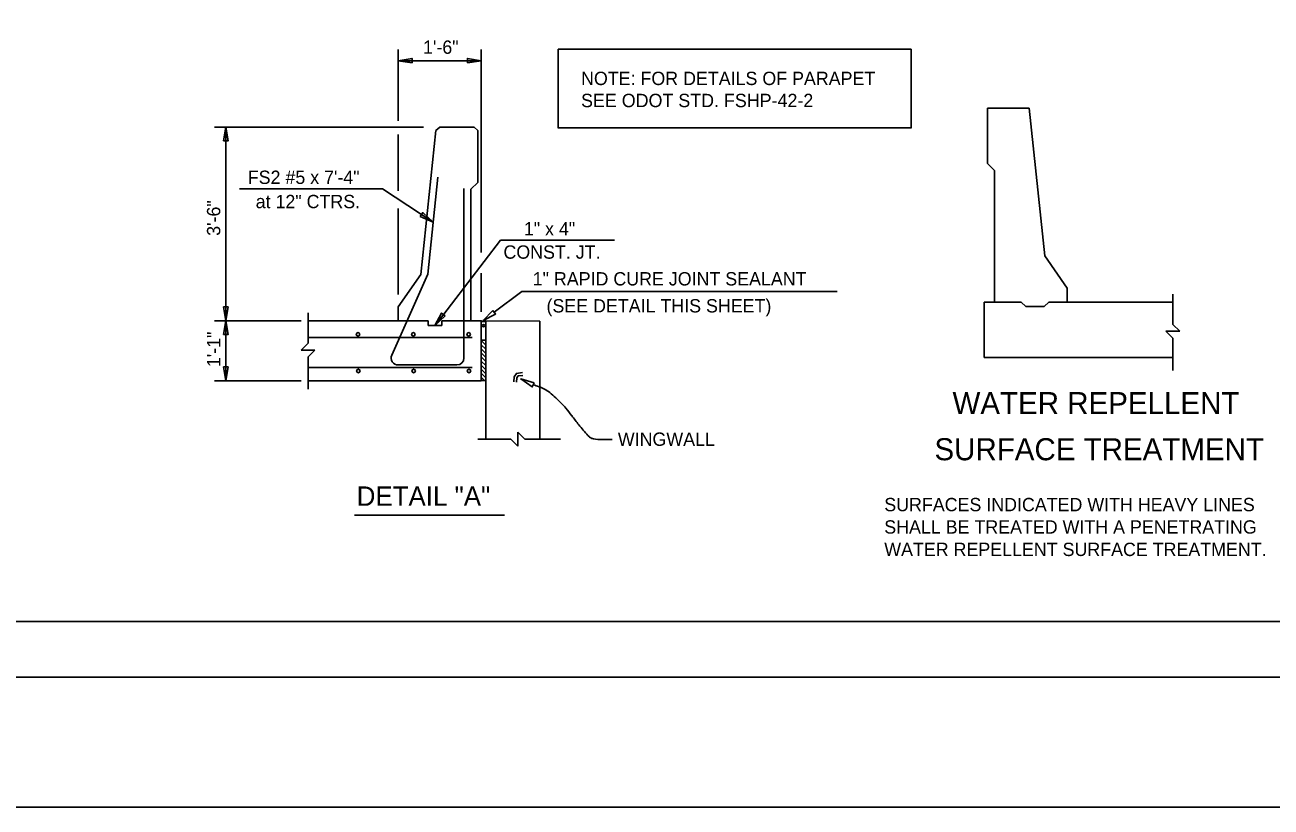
# Model space of a CAD drawing. Extents: x 570 to 2152770, y -27 to 139926.
# Drawn here: x 2151140 to 2151230, y 138735.3 to 138791.8 of the extents above; entities that cross this region are included whole.
import ezdxf

# ---------------------------------------------------------------- set-up
doc = ezdxf.new("R2010")
doc.units = 0
for name, color, linetype in [('2', 7, 'Continuous'), ('4', 7, 'Continuous'), ('5', 7, 'Continuous'), ('6', 7, 'Continuous'), ('Default', 7, 'Continuous'), ('PR_Dimensions', 7, 'Continuous'), ('PR_Reinforcing', 7, 'Continuous'), ('SHT_Plot_Shape_Full', 7, 'Continuous'), ('SHT_Plot_Shape_Half', 7, 'Continuous'), ('SHT_Sheet_Border', 7, 'Continuous'), ('T', 7, 'Continuous')]:
    doc.layers.add(name, color=color, linetype=linetype)

# ---------------------------------------------------------------- blocks, each defined once
blk = doc.blocks.new('DWG01008_2')
at = {"layer": 'Default'}
for p, q in [((-0.0132, 0), (0, 0.0132)), ((0, 0.0132), (0, -0.0132)), ((0, -0.0132), (0.0132, 0))]:
    blk.add_line(p, q, dxfattribs=at)
blk = doc.blocks.new('ARROWHD_7')
at = {"layer": 'Default'}
blk.add_lwpolyline([(0.0261, -0.0045), (0.0261, 0.0043), (-0.0004, -0.0001)], close=True, dxfattribs=at)

msp = doc.modelspace()

# ---------------------------------------------------------------- linework, layer by layer
at = {"layer": '2'}
for p, q in [((2151173.278, 138770.4), (2151173.278, 138761.846)), ((2151173.278, 138770.4), (2151177.175, 138770.362)), ((2151177.175, 138770.362), (2151177.175, 138761.846))]:
    msp.add_line(p, q, dxfattribs=at)
at = {"layer": '4'}
for p, q in [((2151169.668, 138784.15), (2151168.57, 138773.733)), ((2151169.945, 138784.399), (2151169.668, 138784.15)), ((2151172.445, 138784.399), (2151169.945, 138784.399)), ((2151172.445, 138784.399), (2151172.695, 138784.149)), ((2151172.695, 138780.399), (2151172.695, 138784.149)), ((2151172.695, 138780.399), (2151172.195, 138779.899)), ((2151172.195, 138770.4), (2151172.195, 138779.899)), ((2151168.57, 138773.733), (2151166.945, 138771.399)), ((2151166.945, 138770.4), (2151166.945, 138771.399)), ((2151169.111, 138770.4), (2151160.433, 138770.4)), ((2151169.111, 138770.4), (2151169.111, 138770.066)), ((2151170.111, 138770.066), (2151169.111, 138770.066)), ((2151172.945, 138770.4), (2151170.111, 138770.4)), ((2151170.111, 138770.4), (2151170.111, 138770.066)), ((2151172.945, 138770.4), (2151172.945, 138766.066)), ((2151172.945, 138766.066), (2151160.433, 138766.066)), ((2151163.784, 138756.34), (2151174.64, 138756.34))]:
    msp.add_line(p, q, dxfattribs=at)
at = {"layer": '5'}
msp.add_lwpolyline([(2151215.295, 138771.752), (2151215.295, 138772.752), (2151213.67, 138775.085), (2151212.545, 138785.751), (2151209.545, 138785.751)], dxfattribs=at)
at = {"layer": '6'}
for p, q in [((2151209.545, 138781.751), (2151209.545, 138785.751)), ((2151209.545, 138781.751), (2151210.045, 138781.251)), ((2151210.045, 138771.752), (2151210.045, 138781.251)), ((2151209.963, 138771.752), (2151209.297, 138771.752)), ((2151209.297, 138771.752), (2151209.297, 138767.753)), ((2151209.963, 138771.752), (2151211.965, 138771.752)), ((2151211.965, 138771.752), (2151212.298, 138771.419)), ((2151213.964, 138771.752), (2151213.631, 138771.419)), ((2151213.964, 138771.752), (2151222.933, 138771.752)), ((2151222.933, 138770.136), (2151222.933, 138772.316)), ((2151212.298, 138771.419), (2151213.631, 138771.419)), ((2151222.933, 138766.803), (2151222.933, 138769.137)), ((2151209.297, 138767.753), (2151222.933, 138767.753))]:
    msp.add_line(p, q, dxfattribs=at)
at = {"layer": 'PR_Dimensions'}
for p, q in [((2151166.945, 138784.851), (2151166.945, 138789.992)), ((2151172.945, 138775.32), (2151172.945, 138789.992)), ((2151172.945, 138789.192), (2151166.945, 138789.192)), ((2151168.777, 138784.399), (2151153.681, 138784.399)), ((2151154.481, 138770.4), (2151154.481, 138784.399)), ((2151166.945, 138779.785), (2151166.945, 138783.853)), ((2151155.478, 138779.93), (2151165.813, 138779.93)), ((2151169.472, 138777.522), (2151165.813, 138779.93)), ((2151166.945, 138772.301), (2151166.945, 138778.504)), ((2151169.611, 138770.066), (2151174.328, 138776.229)), ((2151182.583, 138776.229), (2151174.328, 138776.229)), ((2151172.945, 138771.047), (2151172.945, 138773.842)), ((2151173.886, 138771.009), (2151175.892, 138772.514)), ((2151175.892, 138772.514), (2151198.683, 138772.514)), ((2151160.433, 138768.784), (2151160.433, 138770.964)), ((2151159.933, 138770.4), (2151153.681, 138770.4)), ((2151154.481, 138770.4), (2151154.481, 138766.066)), ((2151159.933, 138770.4), (2151155.295, 138770.4)), ((2151173.278, 138768.985), (2151172.945, 138768.985)), ((2151173.278, 138768.63), (2151172.945, 138768.963)), ((2151173.278, 138768.335), (2151172.945, 138768.668)), ((2151173.278, 138768.04), (2151172.945, 138768.374)), ((2151173.278, 138767.746), (2151172.945, 138768.079)), ((2151160.433, 138765.449), (2151160.433, 138767.784)), ((2151173.278, 138767.451), (2151172.945, 138767.784)), ((2151173.278, 138767.156), (2151172.945, 138767.49)), ((2151173.278, 138766.862), (2151172.945, 138767.195)), ((2151173.278, 138766.567), (2151172.945, 138766.901)), ((2151173.278, 138766.273), (2151172.945, 138766.606)), ((2151173.184, 138766.072), (2151172.945, 138766.311)), ((2151159.933, 138766.066), (2151153.681, 138766.066)), ((2151173.278, 138766.072), (2151172.945, 138766.072)), ((2151175.096, 138761.846), (2151172.692, 138761.846)), ((2151178.679, 138761.846), (2151176.096, 138761.846))]:
    msp.add_line(p, q, dxfattribs=at)
for points in [[(2151167.945, 138789.026), (2151167.945, 138789.359), (2151166.945, 138789.192)], [(2151171.945, 138789.026), (2151171.945, 138789.359), (2151172.945, 138789.192)], [(2151154.315, 138783.399), (2151154.648, 138783.399), (2151154.481, 138784.399)], [(2151168.541, 138777.935), (2151168.725, 138778.215), (2151169.472, 138777.522)], [(2151154.315, 138771.4), (2151154.648, 138771.4), (2151154.481, 138770.4)], [(2151173.786, 138771.142), (2151173.986, 138770.876), (2151173.086, 138770.409)], [(2151154.315, 138769.398), (2151154.648, 138769.398), (2151154.481, 138770.398)], [(2151154.315, 138767.068), (2151154.648, 138767.068), (2151154.481, 138766.068)], [(2151176.78, 138765.919), (2151176.638, 138765.617), (2151175.804, 138766.193)]]:
    msp.add_lwpolyline(points, close=True, dxfattribs=at)
for points in [[(2151175.92, 138766.647), (2151175.487, 138766.598), (2151175.331, 138766.345), (2151175.308, 138765.975)], [(2151175.943, 138766.45), (2151175.606, 138766.411), (2151175.526, 138766.283), (2151175.506, 138765.962)], [(2151182.416, 138761.807), (2151181.701, 138761.807)]]:
    msp.add_lwpolyline(points, dxfattribs=at)
for centre, radius, start, end in [((2151173.112, 138770.573), 0.24, 226.27744, 313.72256), ((2151173.11, 138770.035), 0.0833, 0, 180), ((2151173.11, 138770.035), 0.0833, 180, 0), ((2151175.038, 138760.167), 5.845, 64.82987, 73.38556), ((2151176.841, 138764.005), 1.604, 48.45934, 64.82987), ((2151161.612, 138746.817), 24.569, 45.78007, 48.45934), ((2151175.873, 138761.471), 4.12, 39.23457, 45.78007), ((2151165.538, 138753.031), 17.464, 36.99349, 39.23457), ((2151200.913, 138779.682), 26.827, 216.99349, 218.80165), ((2151195.05, 138774.968), 19.303, 218.80165, 221.75358), ((2151181.405, 138762.788), 1.014, 221.75358, 234.66211), ((2151181.153, 138762.433), 0.578, 234.66211, 260.10442), ((2151181.701, 138765.574), 3.766, 260.10442, 270)]:
    msp.add_arc(centre, radius, start, end, dxfattribs=at)
at = {"layer": 'PR_Reinforcing'}
for p, q in [((2151169.815, 138780.777), (2151169.077, 138773.777)), ((2151171.695, 138779.947), (2151171.695, 138767.707)), ((2151169.077, 138773.777), (2151166.481, 138767.91)), ((2151172.288, 138769.181), (2151160.433, 138769.181)), ((2151172.288, 138767.014), (2151160.433, 138767.014)), ((2151171.195, 138767.207), (2151166.938, 138767.207))]:
    msp.add_line(p, q, dxfattribs=at)
for centre in [(2151164.042, 138769.412), (2151168.043, 138769.411), (2151172.042, 138769.414), (2151164.065, 138766.772), (2151168.062, 138766.773), (2151172.062, 138766.771)]:
    msp.add_circle(centre, 0.127, dxfattribs=at)
for centre, radius, start, end in [((2151164.042, 138769.415), 0.125, 0, 180), ((2151164.042, 138769.415), 0.125, 180, 0), ((2151168.042, 138769.415), 0.125, 0, 180), ((2151168.042, 138769.415), 0.125, 180, 0), ((2151172.042, 138769.415), 0.125, 0, 180), ((2151172.042, 138769.415), 0.125, 180, 0), ((2151166.938, 138767.707), 0.5, 156.12911, 270), ((2151171.195, 138767.707), 0.5, 270, 0), ((2151164.062, 138766.773), 0.125, 0, 180), ((2151164.062, 138766.773), 0.125, 180, 0), ((2151168.062, 138766.773), 0.125, 0, 180), ((2151168.062, 138766.773), 0.125, 180, 0), ((2151172.062, 138766.773), 0.125, 0, 180), ((2151172.062, 138766.773), 0.125, 180, 0)]:
    msp.add_arc(centre, radius, start, end, dxfattribs=at)
at = {"layer": 'SHT_Plot_Shape_Full'}
msp.add_lwpolyline([(2151027.459, 138927.254), (2151315.459, 138927.254), (2151315.459, 138735.254), (2151027.459, 138735.254)], close=True, dxfattribs=at)
at = {"layer": 'SHT_Plot_Shape_Half'}
msp.add_lwpolyline([(2151040.559, 138920.654), (2151312.559, 138920.654), (2151312.559, 138744.654), (2151040.559, 138744.654)], close=True, dxfattribs=at)
at = {"layer": 'SHT_Sheet_Border'}
msp.add_lwpolyline([(2151308.159, 138748.654), (2151056.159, 138748.654), (2151056.159, 138916.654), (2151308.159, 138916.654)], close=True, dxfattribs=at)
at = {"layer": 'T'}
for p, q in [((2151204.028, 138790.018), (2151178.508, 138790.018)), ((2151178.508, 138790.018), (2151178.508, 138784.324)), ((2151204.028, 138784.324), (2151204.028, 138790.018)), ((2151204.028, 138784.35), (2151178.508, 138784.35))]:
    msp.add_line(p, q, dxfattribs=at)

# ---------------------------------------------------------------- block references
at = {"layer": '6', "xscale": 37.78306610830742, "yscale": 37.78306610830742, "rotation": 90}
msp.add_blockref('DWG01008_2', (2151222.933, 138769.637), dxfattribs=at)
at = {"layer": 'PR_Dimensions', "xscale": 37.7952}
for name, p, yscale, rotation in [('ARROWHD_7', (2151169.611, 138770.066), 37.7952, 52.57268367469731), ('DWG01008_2', (2151160.433, 138768.284), -37.7952, 89.99999999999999), ('DWG01008_2', (2151175.596, 138761.846), -37.7952, 180)]:
    msp.add_blockref(name, p, dxfattribs=dict(at, yscale=yscale, rotation=rotation))

# ---------------------------------------------------------------- texts
at = {"layer": '4'}
for s, height, p in [('WATER REPELLENT', 1.59462, (2151207.007, 138763.649)), ('SURFACE TREATMENT', 1.59462, (2151205.702, 138760.317)), ('DETAIL "A"', 1.4, (2151163.946, 138757.027))]:
    msp.add_text(s, height=height, dxfattribs=at).set_placement(p)
at = {"layer": 'T'}
for s, height, p in [('1\'-6"', 0.9635, (2151168.744, 138789.688)), ('NOTE: FOR DETAILS OF PARAPET', 0.96354, (2151180.162, 138787.431)), ('SEE ODOT STD. FSHP-42-2', 0.9652, (2151180.162, 138785.834)), ('FS2 #5 x 7\'-4"', 0.96354, (2151156.076, 138780.285)), ('at 12" CTRS.', 0.96354, (2151156.645, 138778.533)), ('1" x 4"', 0.9635, (2151176.027, 138776.561)), ('CONST. JT.', 0.9635, (2151174.553, 138774.882)), ('1" RAPID CURE JOINT SEALANT', 0.96354, (2151176.668, 138772.948)), ('(SEE DETAIL THIS SHEET)', 0.96354, (2151177.665, 138770.997)), ('WINGWALL', 0.9635, (2151182.819, 138761.359)), ('SURFACES INDICATED WITH HEAVY LINES ', 0.96354, (2151202.075, 138756.633)), ('SHALL BE TREATED WITH A PENETRATING ', 0.96354, (2151202.075, 138755.014)), ('WATER REPELLENT SURFACE TREATMENT.', 0.96354, (2151202.075, 138753.396))]:
    msp.add_text(s, height=height, dxfattribs=at).set_placement(p)
for s, p in [('3\'-6"', (2151154.087, 138776.538)), ('1\'-1"', (2151154.093, 138767.047))]:
    msp.add_text(s, height=0.9635, rotation=90, dxfattribs=at).set_placement(p)

doc.saveas('drawing.dxf')
